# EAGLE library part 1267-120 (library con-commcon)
.800" BOARD SPACE 2mm CONNECTORS - HI TEMP FOUR ROW 2mm - STACKTHROUGH & NON-STACKTHROUGH
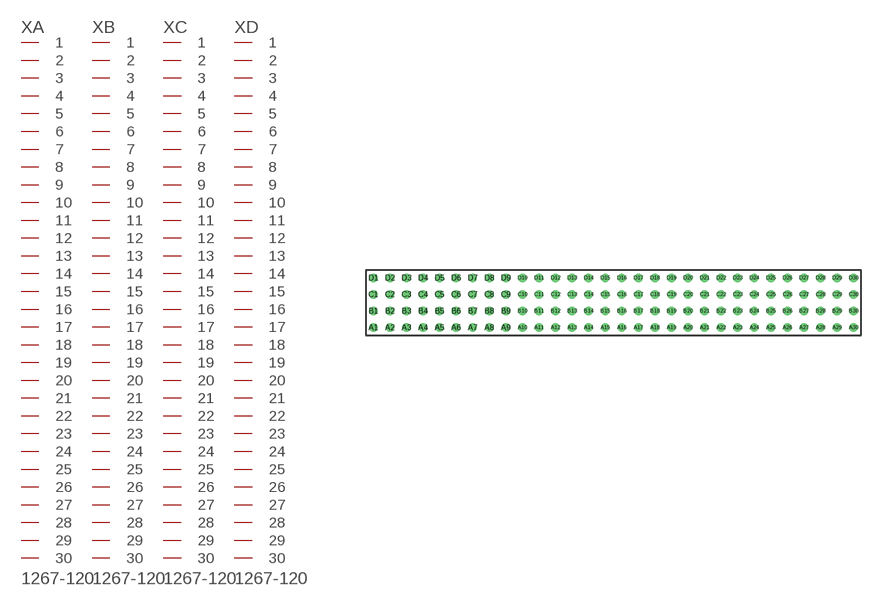
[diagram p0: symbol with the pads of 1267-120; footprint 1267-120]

Designator prefix X; gates A=PIN30 B=PIN30 C=PIN30 D=PIN30

## 1267-120 (OC_FARNELL: unknown; OC_NEWARK: unknown)  [1267-120]
A1  A:1  pas
A2  A:2  pas
A3  A:3  pas
A4  A:4  pas
A5  A:5  pas
A6  A:6  pas
A7  A:7  pas
A8  A:8  pas
A9  A:9  pas
A10  A:10  pas
A11  A:11  pas
A12  A:12  pas
A13  A:13  pas
A14  A:14  pas
A15  A:15  pas
A16  A:16  pas
A17  A:17  pas
A18  A:18  pas
A19  A:19  pas
A20  A:20  pas
A21  A:21  pas
A22  A:22  pas
A23  A:23  pas
A24  A:24  pas
A25  A:25  pas
A26  A:26  pas
A27  A:27  pas
A28  A:28  pas
A29  A:29  pas
A30  A:30  pas
B1  B:1  pas
B2  B:2  pas
B3  B:3  pas
B4  B:4  pas
B5  B:5  pas
B6  B:6  pas
B7  B:7  pas
B8  B:8  pas
B9  B:9  pas
B10  B:10  pas
B11  B:11  pas
B12  B:12  pas
B13  B:13  pas
B14  B:14  pas
B15  B:15  pas
B16  B:16  pas
B17  B:17  pas
B18  B:18  pas
B19  B:19  pas
B20  B:20  pas
B21  B:21  pas
B22  B:22  pas
B23  B:23  pas
B24  B:24  pas
B25  B:25  pas
B26  B:26  pas
B27  B:27  pas
B28  B:28  pas
B29  B:29  pas
B30  B:30  pas
C1  C:1  pas
C2  C:2  pas
C3  C:3  pas
C4  C:4  pas
C5  C:5  pas
C6  C:6  pas
C7  C:7  pas
C8  C:8  pas
C9  C:9  pas
C10  C:10  pas
C11  C:11  pas
C12  C:12  pas
C13  C:13  pas
C14  C:14  pas
C15  C:15  pas
C16  C:16  pas
C17  C:17  pas
C18  C:18  pas
C19  C:19  pas
C20  C:20  pas
C21  C:21  pas
C22  C:22  pas
C23  C:23  pas
C24  C:24  pas
C25  C:25  pas
C26  C:26  pas
C27  C:27  pas
C28  C:28  pas
C29  C:29  pas
C30  C:30  pas
D1  D:1  pas
D2  D:2  pas
D3  D:3  pas
D4  D:4  pas
D5  D:5  pas
D6  D:6  pas
D7  D:7  pas
D8  D:8  pas
D9  D:9  pas
D10  D:10  pas
D11  D:11  pas
D12  D:12  pas
D13  D:13  pas
D14  D:14  pas
D15  D:15  pas
D16  D:16  pas
D17  D:17  pas
D18  D:18  pas
D19  D:19  pas
D20  D:20  pas
D21  D:21  pas
D22  D:22  pas
D23  D:23  pas
D24  D:24  pas
D25  D:25  pas
D26  D:26  pas
D27  D:27  pas
D28  D:28  pas
D29  D:29  pas
D30  D:30  pas

## Footprint 1267-120 (pad centres in mm)
.800" BOARD SPACE 2mm CONNECTORS - HI TEMP FOUR ROW 2mm - STACKTHROUGH & NON-STACKTHROUGH
drill 0.508 round: A1 -29,-3; A2 -27,-3; A3 -25,-3; A4 -23,-3; A5 -21,-3; A6 -19,-3; A7 -17,-3; A8 -15,-3; A9 -13,-3; A10 -11,-3; A11 -9,-3; A12 -7,-3; A13 -5,-3; A14 -3,-3; A15 -1,-3; A16 1,-3; A17 3,-3; A18 5,-3; A19 7,-3; A20 9,-3; A21 11,-3; A22 13,-3; A23 15,-3; A24 17,-3; A25 19,-3; A26 21,-3; A27 23,-3; A28 25,-3; A29 27,-3; A30 29,-3; B1 -29,-1; B2 -27,-1; B3 -25,-1; B4 -23,-1; B5 -21,-1; B6 -19,-1; B7 -17,-1; B8 -15,-1; B9 -13,-1; B10 -11,-1; B11 -9,-1; B12 -7,-1; B13 -5,-1; B14 -3,-1; B15 -1,-1; B16 1,-1; B17 3,-1; B18 5,-1; B19 7,-1; B20 9,-1; B21 11,-1; B22 13,-1; B23 15,-1; B24 17,-1; B25 19,-1; B26 21,-1; B27 23,-1; B28 25,-1; B29 27,-1; B30 29,-1; C1 -29,1; C2 -27,1; C3 -25,1; C4 -23,1; C5 -21,1; C6 -19,1; C7 -17,1; C8 -15,1; C9 -13,1; C10 -11,1; C11 -9,1; C12 -7,1; C13 -5,1; C14 -3,1; C15 -1,1; C16 1,1; C17 3,1; C18 5,1; C19 7,1; C20 9,1; C21 11,1; C22 13,1; C23 15,1; C24 17,1; C25 19,1; C26 21,1; C27 23,1; C28 25,1; C29 27,1; C30 29,1; D1 -29,3; D2 -27,3; D3 -25,3; D4 -23,3; D5 -21,3; D6 -19,3; D7 -17,3; D8 -15,3; D9 -13,3; D10 -11,3; D11 -9,3; D12 -7,3; D13 -5,3; D14 -3,3; D15 -1,3; D16 1,3; D17 3,3; D18 5,3; D19 7,3; D20 9,3; D21 11,3; D22 13,3; D23 15,3; D24 17,3; D25 19,3; D26 21,3; D27 23,3; D28 25,3; D29 27,3; D30 29,3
